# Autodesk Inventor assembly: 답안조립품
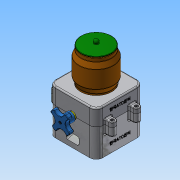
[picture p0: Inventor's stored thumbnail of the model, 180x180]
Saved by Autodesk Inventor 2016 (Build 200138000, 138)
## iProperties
Created: 2018-01
Part Number: 답안조립품
Material: 일반
Document SubType Name: Assembly
Designer: Administrator
Author: Administrator
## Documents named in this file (9)
- C:\Users\Administrator\Desktop\480107V1021\답안조립품.iam
- C:\Users\Administrator\Desktop\480107V1021\본체.ipt
- C:\Users\Administrator\Desktop\480107V1021\핸들축.ipt
- C:\Users\Administrator\Desktop\480107V1021\핸들.ipt
- C:\Users\Administrator\Desktop\480107V1021\볼트 M3x12.ipt
- C:\Users\Administrator\Desktop\480107V1021\용기.ipt
- C:\Users\Administrator\Desktop\480107V1021\용기캡.ipt
- C:\Users\Administrator\Desktop\480107V1021\본체커버.ipt
- C:\Users\Administrator\Desktop\480107V1021\볼트 M4x12.ipt
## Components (2 placed, 2 different names)
1. 핸들축:1
2. 핸들:1
